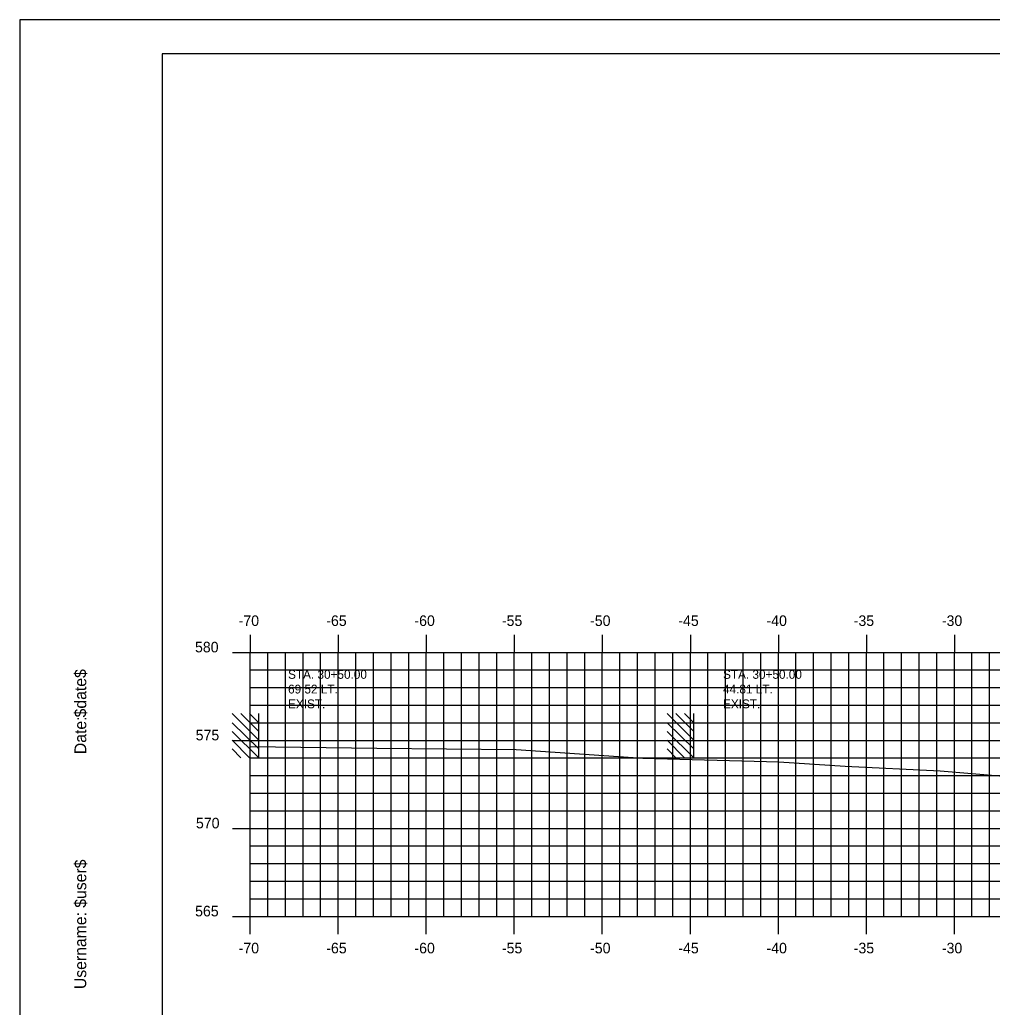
# Model space of a CAD drawing. Extents: x 1048109 to 1048279, y 781630 to 781740.
# Drawn here: x 1048108.6 to 1048163.9, y 781684 to 781740.1 of the extents above; entities that cross this region are included whole.
import ezdxf

# ---------------------------------------------------------------- set-up
doc = ezdxf.new("R2010")
doc.units = 0
for name, color, linetype in [('D_Text_Monospaced', 7, 'Continuous'), ('Default', 7, 'Continuous'), ('H_V ANNOTATION', 7, 'Continuous'), ('MAJOR', 7, 'Continuous'), ('MINOR', 7, 'Continuous'), ('S_Buildings_Canopy_Carport', 7, 'Continuous'), ('S_Roadway_Centerline', 7, 'Continuous')]:
    doc.layers.add(name, color=color, linetype=linetype)

msp = doc.modelspace()

# ---------------------------------------------------------------- linework, layer by layer
at = {"layer": 'Default'}
for p, q in [((1048276.734, 781738.195), (1048116.734, 781738.195)), ((1048116.734, 781738.195), (1048116.734, 781633.195))]:
    msp.add_line(p, q, dxfattribs=at)
msp.add_lwpolyline([(1048108.64, 781630.136), (1048278.64, 781630.136), (1048278.64, 781740.136), (1048108.64, 781740.136)], close=True, dxfattribs=at)
at = {"layer": 'MAJOR'}
for p, q in [((1048121.733, 781705.197), (1048121.733, 781704.195)), ((1048121.733, 781705.197), (1048121.733, 781704.195)), ((1048126.733, 781705.197), (1048126.733, 781704.195)), ((1048126.733, 781705.197), (1048126.733, 781704.195)), ((1048131.733, 781705.197), (1048131.733, 781704.195)), ((1048131.733, 781705.197), (1048131.733, 781704.195)), ((1048136.733, 781705.197), (1048136.733, 781704.195)), ((1048136.733, 781705.197), (1048136.733, 781704.195)), ((1048141.733, 781705.197), (1048141.733, 781704.195)), ((1048141.733, 781705.197), (1048141.733, 781704.195)), ((1048146.733, 781705.197), (1048146.733, 781704.195)), ((1048146.733, 781705.197), (1048146.733, 781704.195)), ((1048151.733, 781705.197), (1048151.733, 781704.195)), ((1048151.733, 781705.197), (1048151.733, 781704.195)), ((1048156.733, 781705.197), (1048156.733, 781704.195)), ((1048156.733, 781705.197), (1048156.733, 781704.195)), ((1048161.733, 781705.197), (1048161.733, 781704.195)), ((1048161.733, 781705.197), (1048161.733, 781704.195)), ((1048120.731, 781704.195), (1048121.733, 781704.195)), ((1048120.731, 781704.195), (1048121.733, 781704.195)), ((1048121.733, 781704.195), (1048261.733, 781704.195)), ((1048121.733, 781689.195), (1048121.733, 781704.195)), ((1048121.733, 781689.195), (1048121.733, 781704.195)), ((1048121.733, 781704.195), (1048261.733, 781704.195)), ((1048121.733, 781704.195), (1048261.733, 781704.195)), ((1048121.733, 781689.195), (1048121.733, 781704.195)), ((1048121.733, 781689.195), (1048121.733, 781704.195)), ((1048121.733, 781704.195), (1048261.733, 781704.195)), ((1048126.733, 781689.195), (1048126.733, 781704.195)), ((1048126.733, 781689.195), (1048126.733, 781704.195)), ((1048131.733, 781689.195), (1048131.733, 781704.195)), ((1048131.733, 781689.195), (1048131.733, 781704.195)), ((1048136.733, 781689.195), (1048136.733, 781704.195)), ((1048136.733, 781689.195), (1048136.733, 781704.195)), ((1048141.733, 781689.195), (1048141.733, 781704.195)), ((1048141.733, 781689.195), (1048141.733, 781704.195)), ((1048146.733, 781689.195), (1048146.733, 781704.195)), ((1048146.733, 781689.195), (1048146.733, 781704.195)), ((1048151.733, 781689.195), (1048151.733, 781704.195)), ((1048151.733, 781689.195), (1048151.733, 781704.195)), ((1048156.733, 781689.195), (1048156.733, 781704.195)), ((1048156.733, 781689.195), (1048156.733, 781704.195)), ((1048161.733, 781689.195), (1048161.733, 781704.195)), ((1048161.733, 781689.195), (1048161.733, 781704.195)), ((1048120.731, 781699.195), (1048121.733, 781699.195)), ((1048120.731, 781699.195), (1048121.733, 781699.195)), ((1048121.733, 781699.195), (1048261.733, 781699.195)), ((1048121.733, 781699.195), (1048261.733, 781699.195)), ((1048120.731, 781694.195), (1048121.733, 781694.195)), ((1048120.731, 781694.195), (1048121.733, 781694.195)), ((1048121.733, 781694.195), (1048261.733, 781694.195)), ((1048121.733, 781694.195), (1048261.733, 781694.195)), ((1048120.731, 781689.195), (1048121.733, 781689.195)), ((1048120.731, 781689.195), (1048121.733, 781689.195)), ((1048121.733, 781689.195), (1048261.733, 781689.195)), ((1048121.733, 781689.195), (1048261.733, 781689.195)), ((1048121.733, 781688.193), (1048121.733, 781689.195)), ((1048121.733, 781689.195), (1048261.733, 781689.195)), ((1048121.733, 781689.195), (1048261.733, 781689.195)), ((1048121.733, 781688.193), (1048121.733, 781689.195)), ((1048126.733, 781688.193), (1048126.733, 781689.195)), ((1048126.733, 781688.193), (1048126.733, 781689.195)), ((1048131.733, 781688.193), (1048131.733, 781689.195)), ((1048131.733, 781688.193), (1048131.733, 781689.195)), ((1048136.733, 781688.193), (1048136.733, 781689.195)), ((1048136.733, 781688.193), (1048136.733, 781689.195)), ((1048141.733, 781688.193), (1048141.733, 781689.195)), ((1048141.733, 781688.193), (1048141.733, 781689.195)), ((1048146.733, 781688.193), (1048146.733, 781689.195)), ((1048146.733, 781688.193), (1048146.733, 781689.195)), ((1048151.733, 781688.193), (1048151.733, 781689.195)), ((1048151.733, 781688.193), (1048151.733, 781689.195)), ((1048156.733, 781688.193), (1048156.733, 781689.195)), ((1048156.733, 781688.193), (1048156.733, 781689.195)), ((1048161.733, 781688.193), (1048161.733, 781689.195)), ((1048161.733, 781688.193), (1048161.733, 781689.195))]:
    msp.add_line(p, q, dxfattribs=at)
at = {"layer": 'MINOR'}
for p, q in [((1048122.733, 781689.195), (1048122.733, 781704.195)), ((1048122.733, 781689.195), (1048122.733, 781704.195)), ((1048123.733, 781689.195), (1048123.733, 781704.195)), ((1048123.733, 781689.195), (1048123.733, 781704.195)), ((1048124.733, 781689.195), (1048124.733, 781704.195)), ((1048124.733, 781689.195), (1048124.733, 781704.195)), ((1048125.733, 781689.195), (1048125.733, 781704.195)), ((1048125.733, 781689.195), (1048125.733, 781704.195)), ((1048127.733, 781689.195), (1048127.733, 781704.195)), ((1048127.733, 781689.195), (1048127.733, 781704.195)), ((1048128.733, 781689.195), (1048128.733, 781704.195)), ((1048128.733, 781689.195), (1048128.733, 781704.195)), ((1048129.733, 781689.195), (1048129.733, 781704.195)), ((1048129.733, 781689.195), (1048129.733, 781704.195)), ((1048130.733, 781689.195), (1048130.733, 781704.195)), ((1048130.733, 781689.195), (1048130.733, 781704.195)), ((1048132.733, 781689.195), (1048132.733, 781704.195)), ((1048132.733, 781689.195), (1048132.733, 781704.195)), ((1048133.733, 781689.195), (1048133.733, 781704.195)), ((1048133.733, 781689.195), (1048133.733, 781704.195)), ((1048134.733, 781689.195), (1048134.733, 781704.195)), ((1048134.733, 781689.195), (1048134.733, 781704.195)), ((1048135.733, 781689.195), (1048135.733, 781704.195)), ((1048135.733, 781689.195), (1048135.733, 781704.195)), ((1048137.733, 781689.195), (1048137.733, 781704.195)), ((1048137.733, 781689.195), (1048137.733, 781704.195)), ((1048138.733, 781689.195), (1048138.733, 781704.195)), ((1048138.733, 781689.195), (1048138.733, 781704.195)), ((1048139.733, 781689.195), (1048139.733, 781704.195)), ((1048139.733, 781689.195), (1048139.733, 781704.195)), ((1048140.733, 781689.195), (1048140.733, 781704.195)), ((1048140.733, 781689.195), (1048140.733, 781704.195)), ((1048142.733, 781689.195), (1048142.733, 781704.195)), ((1048142.733, 781689.195), (1048142.733, 781704.195)), ((1048143.733, 781689.195), (1048143.733, 781704.195)), ((1048143.733, 781689.195), (1048143.733, 781704.195)), ((1048144.733, 781689.195), (1048144.733, 781704.195)), ((1048144.733, 781689.195), (1048144.733, 781704.195)), ((1048145.733, 781689.195), (1048145.733, 781704.195)), ((1048145.733, 781689.195), (1048145.733, 781704.195)), ((1048147.733, 781689.195), (1048147.733, 781704.195)), ((1048147.733, 781689.195), (1048147.733, 781704.195)), ((1048148.733, 781689.195), (1048148.733, 781704.195)), ((1048148.733, 781689.195), (1048148.733, 781704.195)), ((1048149.733, 781689.195), (1048149.733, 781704.195)), ((1048149.733, 781689.195), (1048149.733, 781704.195)), ((1048150.733, 781689.195), (1048150.733, 781704.195)), ((1048150.733, 781689.195), (1048150.733, 781704.195)), ((1048152.733, 781689.195), (1048152.733, 781704.195)), ((1048152.733, 781689.195), (1048152.733, 781704.195)), ((1048153.733, 781689.195), (1048153.733, 781704.195)), ((1048153.733, 781689.195), (1048153.733, 781704.195)), ((1048154.733, 781689.195), (1048154.733, 781704.195)), ((1048154.733, 781689.195), (1048154.733, 781704.195)), ((1048155.733, 781689.195), (1048155.733, 781704.195)), ((1048155.733, 781689.195), (1048155.733, 781704.195)), ((1048157.733, 781689.195), (1048157.733, 781704.195)), ((1048157.733, 781689.195), (1048157.733, 781704.195)), ((1048158.733, 781689.195), (1048158.733, 781704.195)), ((1048158.733, 781689.195), (1048158.733, 781704.195)), ((1048159.733, 781689.195), (1048159.733, 781704.195)), ((1048159.733, 781689.195), (1048159.733, 781704.195)), ((1048160.733, 781689.195), (1048160.733, 781704.195)), ((1048160.733, 781689.195), (1048160.733, 781704.195)), ((1048162.733, 781689.195), (1048162.733, 781704.195)), ((1048162.733, 781689.195), (1048162.733, 781704.195)), ((1048163.733, 781689.195), (1048163.733, 781704.195)), ((1048163.733, 781689.195), (1048163.733, 781704.195)), ((1048121.733, 781703.195), (1048261.733, 781703.195)), ((1048121.733, 781703.195), (1048122.735, 781703.195)), ((1048121.733, 781703.195), (1048261.733, 781703.195)), ((1048121.733, 781703.195), (1048122.735, 781703.195)), ((1048121.733, 781702.195), (1048261.733, 781702.195)), ((1048121.733, 781702.195), (1048122.735, 781702.195)), ((1048121.733, 781702.195), (1048261.733, 781702.195)), ((1048121.733, 781702.195), (1048122.735, 781702.195)), ((1048121.733, 781701.195), (1048261.733, 781701.195)), ((1048121.733, 781701.195), (1048122.735, 781701.195)), ((1048121.733, 781701.195), (1048261.733, 781701.195)), ((1048121.733, 781701.195), (1048122.735, 781701.195)), ((1048121.733, 781700.195), (1048261.733, 781700.195)), ((1048121.733, 781700.195), (1048122.735, 781700.195)), ((1048121.733, 781700.195), (1048261.733, 781700.195)), ((1048121.733, 781700.195), (1048122.735, 781700.195)), ((1048121.733, 781698.195), (1048261.733, 781698.195)), ((1048121.733, 781698.195), (1048122.735, 781698.195)), ((1048121.733, 781698.195), (1048261.733, 781698.195)), ((1048121.733, 781698.195), (1048122.735, 781698.195)), ((1048121.733, 781697.195), (1048261.733, 781697.195)), ((1048121.733, 781697.195), (1048122.735, 781697.195)), ((1048121.733, 781697.195), (1048187.041, 781697.195)), ((1048121.733, 781697.195), (1048122.735, 781697.195)), ((1048121.733, 781696.195), (1048261.733, 781696.195)), ((1048121.733, 781696.195), (1048122.735, 781696.195)), ((1048121.733, 781696.195), (1048261.733, 781696.195)), ((1048121.733, 781696.195), (1048122.735, 781696.195)), ((1048121.733, 781695.195), (1048261.733, 781695.195)), ((1048121.733, 781695.195), (1048122.735, 781695.195)), ((1048121.733, 781695.195), (1048261.733, 781695.195)), ((1048121.733, 781695.195), (1048122.735, 781695.195)), ((1048121.733, 781693.195), (1048261.733, 781693.195)), ((1048121.733, 781693.195), (1048122.735, 781693.195)), ((1048121.733, 781693.195), (1048261.733, 781693.195)), ((1048121.733, 781693.195), (1048122.735, 781693.195)), ((1048121.733, 781692.195), (1048261.733, 781692.195)), ((1048121.733, 781692.195), (1048122.735, 781692.195)), ((1048121.733, 781692.195), (1048261.733, 781692.195)), ((1048121.733, 781692.195), (1048122.735, 781692.195)), ((1048121.733, 781691.195), (1048261.733, 781691.195)), ((1048121.733, 781691.195), (1048122.735, 781691.195)), ((1048121.733, 781691.195), (1048261.733, 781691.195)), ((1048121.733, 781691.195), (1048122.735, 781691.195)), ((1048121.733, 781690.195), (1048261.733, 781690.195)), ((1048121.733, 781690.195), (1048122.735, 781690.195)), ((1048121.733, 781690.195), (1048261.733, 781690.195)), ((1048121.733, 781690.195), (1048122.735, 781690.195))]:
    msp.add_line(p, q, dxfattribs=at)
at = {"layer": 'S_Buildings_Canopy_Carport'}
for p, q in [((1048122.215, 781699.212), (1048120.706, 781700.721)), ((1048122.215, 781699.704), (1048121.198, 781700.721)), ((1048122.215, 781700.196), (1048121.69, 781700.721)), ((1048122.215, 781698.195), (1048122.215, 781700.721)), ((1048146.923, 781699.212), (1048145.414, 781700.721)), ((1048146.923, 781699.704), (1048145.906, 781700.721)), ((1048146.923, 781700.196), (1048146.398, 781700.721)), ((1048146.923, 781698.195), (1048146.923, 781700.721)), ((1048122.215, 781698.72), (1048120.706, 781700.196)), ((1048146.923, 781698.72), (1048145.414, 781700.196)), ((1048122.215, 781698.195), (1048120.706, 781699.704)), ((1048146.923, 781698.195), (1048145.414, 781699.704)), ((1048121.69, 781698.195), (1048120.706, 781699.212)), ((1048146.398, 781698.195), (1048145.414, 781699.212)), ((1048121.198, 781698.195), (1048120.706, 781698.72)), ((1048145.906, 781698.195), (1048145.414, 781698.72))]:
    msp.add_line(p, q, dxfattribs=at)
at = {"layer": 'S_Roadway_Centerline'}
msp.add_lwpolyline([(1048121.733, 781698.855), (1048128.917, 781698.744), (1048136.847, 781698.674), (1048144.033, 781698.186), (1048151.759, 781697.984), (1048155.521, 781697.733), (1048160.931, 781697.459), (1048164.515, 781697.164)], dxfattribs=at)

# ---------------------------------------------------------------- texts
at = {"layer": 'D_Text_Monospaced'}
for s, height, p in [('STA. 30+50.00', 0.49998, (1048123.882, 781702.693)), ('STA. 30+50.00', 0.49998, (1048148.59, 781702.693)), ('69.52 LT.', 0.5, (1048123.882, 781701.859)), ('44.81 LT.', 0.5, (1048148.59, 781701.859)), ('EXIST. ', 0.5, (1048123.882, 781701.019)), ('EXIST. ', 0.5, (1048148.59, 781701.019))]:
    msp.add_text(s, height=height, dxfattribs=at).set_placement(p)
at = {"layer": 'Default'}
for s, p in [('$date$', (1048112.418, 781700.501)), ('Date:', (1048112.418, 781698.412)), ('$user$', (1048112.418, 781689.687)), ('Username:', (1048112.418, 781685.063))]:
    msp.add_text(s, height=0.6696, rotation=90, dxfattribs=at).set_placement(p)
at = {"layer": 'H_V ANNOTATION'}
for s, p in [('-70', (1048121.075, 781705.695)), ('-65', (1048126.051, 781705.695)), ('-60', (1048131.059, 781705.695)), ('-55', (1048136.029, 781705.695)), ('-50', (1048141.038, 781705.695)), ('-45', (1048146.051, 781705.695)), ('-40', (1048151.059, 781705.695)), ('-35', (1048156.014, 781705.695)), ('-30', (1048161.022, 781705.695)), ('580', (1048118.595, 781704.195)), ('575', (1048118.633, 781699.195)), ('570', (1048118.649, 781694.195)), ('565', (1048118.601, 781689.195)), ('-70', (1048121.075, 781687.095)), ('-65', (1048126.051, 781687.095)), ('-60', (1048131.059, 781687.095)), ('-55', (1048136.029, 781687.095)), ('-50', (1048141.038, 781687.095)), ('-45', (1048146.051, 781687.095)), ('-40', (1048151.059, 781687.095)), ('-35', (1048156.014, 781687.095)), ('-30', (1048161.022, 781687.095))]:
    msp.add_text(s, height=0.6, dxfattribs=at).set_placement(p)
at = {"layer": 'MAJOR'}
msp.add_text('-', height=0.006, dxfattribs=at).set_placement((1048121.729, 781689.195))
msp.add_text('-', height=0.006, dxfattribs=at).set_placement((1048121.729, 781689.195))

doc.saveas('drawing.dxf')
